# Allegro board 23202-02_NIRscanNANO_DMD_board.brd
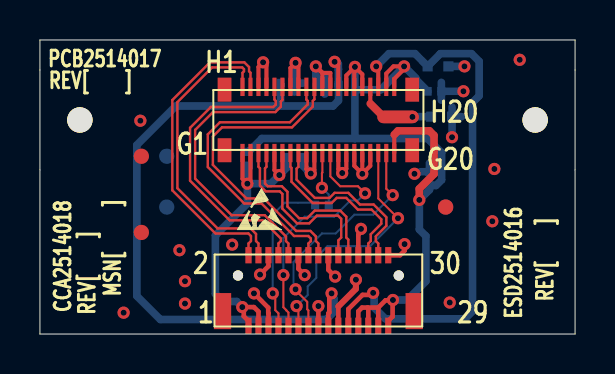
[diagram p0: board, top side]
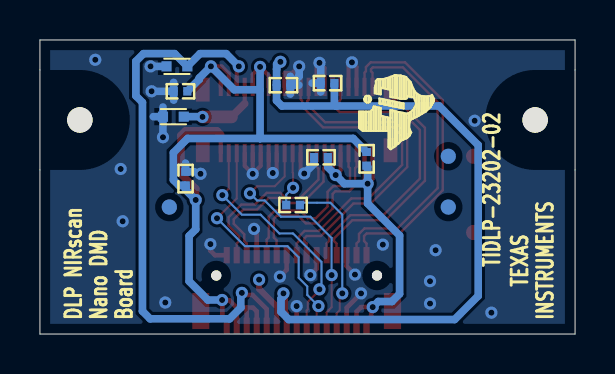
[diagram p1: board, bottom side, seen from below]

Outline 26.8 x 14.71 mm; copper layers: TOP, LY2GND, LY3PLANE, BOTTOM. Coordinates in mm from the lower left corner of the outline.
Outline path: 0,14.71 0,0 26.8,0 26.8,14.71 0,14.71

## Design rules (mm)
net group DIFFPAIR0: nets DMD_HS_WDATAA_N DMD_HS_WDATAA_P
net group DMD_HS_CLK_: nets DMD_HS_CLK_N DMD_HS_CLK_P
net group DMD_HS_WDATAB_: nets DMD_HS_WDATAB_N DMD_HS_WDATAB_P
net group DMD_HS_WDATAG_: nets DMD_HS_WDATAG_N DMD_HS_WDATAG_P
net group DMD_HS_WDATAH_: nets DMD_HS_WDATAH_N DMD_HS_WDATAH_P
net group 68OHM: nets DMD_DEN_ARSTZ DMD_LS_CLK DMD_LS_RDATA DMD_LS_RDATA_T DMD_LS_WDATA
net group PWR: nets VBIAS VCC VCCI VOFS VRST

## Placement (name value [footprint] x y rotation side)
C1  -  [0201]  12.73 8.84 0 bottom
C2  -  [0201]  19.51 7.77 90 bottom
C3  -  [0201]  19.76 12.14 0 bottom
C4  -  [0402]  20.12 10.87 0 bottom
C5  -  [0201]  12.4 12.55 0 bottom
C6  -  [0201]  14.61 12.45 180 bottom
C7  -  [0402]  19.94 13.39 0 bottom
FID  -  [unnamed#3]  5.08 8.89 0 top
FID#2  -  [unnamed#3]  20.32 6.35 0 top
FID#3  -  [unnamed#3]  5.08 5.08 0 top
FID#4  -  [unnamed#3]  20.32 6.35 180 bottom
FID#5  -  [unnamed#3]  6.35 8.89 180 bottom
FID#6  -  [unnamed#3]  6.35 6.35 180 bottom
J1  -  [CONN30-JMCS-G-1B-TF_JST]  13.94 2.18 0 top
J2  -  [CONN40-AXT540124-GH_PAN]  13.94 10.71 0 top
NOREF  -  []  0 0 0 top
NOREF#2  -  [unnamed#2]  2 10.71 0 top
NOREF#3  -  []  11.1 6.15 0 top
NOREF#4  -  []  0 0 0 top
NOREF#5  -  []  67.55 13.92 0 top
NOREF#6  -  []  0 0 90 top
NOREF#7  -  []  -19.05 31.75 0 top
NOREF#8  -  []  44.45 31.75 0 top
NOREF#9  -  []  -115.46 -53.59 0 top
NOREF#10  -  [unnamed#2]  24.8 10.71 0 top
NOREF#11  -  []  -19.05 -12.7 0 top
NOREF#12  -  []  0 0 90 top
NOREF#13  -  []  9.19 11.15 90 bottom
R1  -  [0201]  10.44 8.76 90 bottom
R2  -  [0201]  14.12 6.45 0 bottom

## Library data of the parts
C1-C3 C5 C6 R1 R2 = 0201
C4 C7 = 0402: alternate symbols: (0402-1mm)
J1 = CONN30-JMCS-G-1B-TF_JST
J2 = CONN40-AXT540124-GH_PAN

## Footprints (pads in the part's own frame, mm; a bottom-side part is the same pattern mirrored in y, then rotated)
0201
  rect 0.406x0.432 smd: 1(-0.343,0) 2(0.343,0)
0402
  rect 0.508x0.508 smd: 1(-0.521,0) 2(0.521,0)
CONN30-JMCS-G-1B-TF_JST
  round 0.508 hole 0.686 unplated: (-4.025,0.75) (4.025,0.75)
  rect 0.305x0.813 smd: 1(-3.5,-1.765) 2(-3.5,1.765) 3(-3,-1.765) 4(-3,1.765) 5(-2.5,-1.765) 6(-2.5,1.765) 7(-2,-1.765) 8(-2,1.765) 9(-1.5,-1.765) 10(-1.5,1.765) 11(-1,-1.765) 12(-1,1.765) 13(-0.5,-1.765) 14(-0.5,1.765) 15(0,-1.765) 16(0,1.765) 17(0.5,-1.765) 18(0.5,1.765) 19(1,-1.765) 20(1,1.765) 21(1.5,-1.765) 22(1.5,1.765) 23(2,-1.765) 24(2,1.765) 25(2.5,-1.765) 26(2.5,1.765) 27(3,-1.765) 28(3,1.765) 29(3.5,-1.765) 30(3.5,1.765)
  rect 0.864x1.803 smd: 31(-4.8,-1.03) 32(4.8,-1.03)
CONN40-AXT540124-GH_PAN
  rect 0.686x1.194 smd: 41(-4.7,1.515) 42(-4.7,-1.515) 43(4.7,1.515) 44(4.7,-1.515)
  rect 0.203x0.914 smd: G1(-3.8,-1.655) G2(-3.4,-1.655) G3(-3,-1.655) G4(-2.6,-1.655) G5(-2.2,-1.655) G6(-1.8,-1.655) G7(-1.4,-1.655) G8(-1,-1.655) G9(-0.6,-1.655) G10(-0.2,-1.655) G11(0.2,-1.655) G12(0.6,-1.655) G13(1,-1.655) G14(1.4,-1.655) G15(1.8,-1.655) G16(2.2,-1.655) G17(2.6,-1.655) G18(3,-1.655) G19(3.4,-1.655) G20(3.8,-1.655) H1(-3.8,1.655) H2(-3.4,1.655) H3(-3,1.655) H4(-2.6,1.655) H5(-2.2,1.655) H6(-1.8,1.655) H7(-1.4,1.655) H8(-1,1.655) H9(-0.6,1.655) H10(-0.2,1.655) H11(0.2,1.655) H12(0.6,1.655) H13(1,1.655) H14(1.4,1.655) H15(1.8,1.655) H16(2.2,1.655) H17(2.6,1.655) H18(3,1.655) H19(3.4,1.655) H20(3.8,1.655)
unnamed#2
  round 1.27 hole 2.499 unplated: (0,0)
unnamed#3
  round 0.762 smd: 1(0,0)

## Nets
GND: C1.2 C2.2 C3.2 C4.2 C5.2 C6.2 C7.2 J1.5 J1.6 J1.12 J1.15 J1.18 J1.24 J1.30 J2.G9 J2.G10 J2.G13 J2.G14 J2.G15 J2.G16 J2.G17 J2.H3 J2.H4 J2.H7 J2.H8 J2.H11 J2.H12
VCC: C2.1 C3.1 J1.23 J1.25 J1.27 J1.29 J2.G20 J2.H14 J2.H15 J2.H16 J2.H19 J2.H20 R1.2
VCCI: C1.1 J1.1 J1.3 J2.G1 J2.G2 J2.G5 J2.G6 R1.1
DMD_DEN_ARSTZ: J1.9 J2.G12
DMD_HS_CLK_N: J1.14 J2.H9
DMD_HS_CLK_P: J1.16 J2.H10
DMD_HS_WDATAA_N: J1.4 J2.H1
DMD_HS_WDATAA_P: J1.2 J2.H2
DMD_HS_WDATAB_N: J1.8 J2.H5
DMD_HS_WDATAB_P: J1.10 J2.H6
DMD_HS_WDATAG_N: J1.28 J2.G8
DMD_HS_WDATAG_P: J1.26 J2.G7
DMD_HS_WDATAH_N: J1.22 J2.G4
DMD_HS_WDATAH_P: J1.20 J2.G3
DMD_LS_CLK: J1.13 J2.G19
DMD_LS_RDATA: J1.7 R2.1
DMD_LS_RDATA_T: J2.G11 R2.2
DMD_LS_WDATA: J1.11 J2.G18
VBIAS: C4.1 J1.19 J2.H17
VOFS: C5.1 C6.1 J1.17 J2.H13
VRST: C7.1 J1.21 J2.H18

Pads without a net: FID 1; FID#2 1; FID#3 1; FID#4 1; FID#5 1; FID#6 1; J1 31 32; J2 41 42 43 44

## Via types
v1: diameter 0.61, hole 0.305, TOP to BOTTOM, 48 vias

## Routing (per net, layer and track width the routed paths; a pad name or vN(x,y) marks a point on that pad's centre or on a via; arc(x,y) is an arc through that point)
GND: length 35.3
  TOP w0.203: J2.G14 15.34,8.26 v1(15.14,8.05) 14.94,8.25 J2.G13 ; J2.G10 13.74,8.21 v1(13.56,8.03) 13.34,8.25 J2.G9 ; J2.G17 16.54,8.41 v1(16.14,8.01) ; J2.H8 12.94,13.42 v1(12.8,13.56) 12.54,13.31 J2.H7 ; J2.H3 10.94,13.36 v1(11.18,13.59) 11.34,13.42 J2.H4 ; J2.G15 15.74,8.41 v1(16.14,8.01) ; J2.H11 14.14,13.06 14.54,13.06 J2.H12 ; v1(16.14,8.01) J2.G16
  TOP w0.229: J1.15 v1(13.94,1.4) ; J1.24 15.94,4.97 16.08,5.11 v1(16.08,5.26) ; 14.14,13.06 v1(13.82,13.39) ; v1(14.78,2.87) 14.44,3.21 J1.18 ; v1(10.72,2.03) 11.43,1.32 11.43,1.05 11.44,1.04 J1.5 ; v1(11.02,2.97) 11.44,3.39 J1.6 ; J1.12 12.94,3.26 v1(13.26,2.95) ; J1.30 18.03,3.94 18.26,4.17 v1(18.26,4.5)
  BOTTOM w0.381: v1(13.56,8.03) 13.07,8.52 C1.2 ; 13.83,12.45 C6.2 ; C6.2 14.26,12.89 ; C6.2 13.82,12.89 v1(13.82,13.39) ; C6.2 14.26,12 ; C5.2 12.74,13.5 v1(12.8,13.56) ; C5.2 12.74,12.1 ; C5.2 13.17,12.55 ; C3.2 v1(21.21,12.14) ; C3.2 20.1,12.59 ; C3.2 20.1,11.7 ; C4.2 21.12,10.87 ; C4.2 20.64,11.35 ; C4.2 v1(20.64,9.84) ; 19.06,8.12 C2.2 19.51,8.55 ; C7.2 v1(21.26,13.39)
  vias: v1(4.19,1.07) v1(5.03,10.67) v1(6.99,4.19) v1(7.26,2.64) v1(7.26,1.52) v1(9.63,4.47) v1(18.76,8.01) v1(20.52,1.57) v1(22.66,5.64) v1(22.76,8.26) v1(24.03,13.72)
VCC: length 46.6
  TOP w0.203: J2.H19 17.34,13.03 17.7,13.39 18.11,13.39 18.24,13.25 17.74,12.76 J2.H20 ; J2.H15 15.74,13.33 15.34,12.93 J2.H14 ; v1(15.78,13.36) 16.14,12.99 J2.H16 ; J2.G20 17.74,9.97
  TOP w0.229: J1.29 17.44,0.66 17.66,0.87 17.66,1.69 ; 17.66,1.69 17.31,1.69 16.94,1.32 ; 17.66,1.69 v1(17.68,1.7) ; J1.27 16.94,1.32 16.94,1.32 ; 16.94,1.32 16.41,1.32 ; 16.41,1.32 16.44,1.28 J1.25 ; 16.41,1.32 16.13,1.32 15.94,1.14 J1.23 ; 18.24,13.25 v1(18.24,13.39) ; 15.74,13.33 v1(15.78,13.36)
  TOP w0.381: 17.74,9.97 17.93,10.16 19.51,10.16 19.74,9.93 19.74,8 19,7.26 v1(19,6.71)
  BOTTOM w0.381: 15.78,9.78 19.4,9.78 20.12,9.07 20.12,7.71 19.84,7.43 C2.1 19.51,7.21 v1(19,6.71) 19,5.23 19.33,4.9 19.33,2.64 18.39,1.7 v1(17.68,1.7) ; 15.78,9.78 15.77,9.78 11.11,9.78 R1.2 ; 15.78,9.78 15.78,12.22 ; C3.1 18.82,12.74 18.82,12.8 v1(18.24,13.39) 17.07,12.22 15.78,12.22 ; 15.78,12.22 v1(15.78,13.36)
VCCI: length 19.8
  TOP w0.203: J2.G1 10.14,7.76 v1(10.39,7.52) 10.54,7.67 J2.G2 ; J2.G5 11.74,8.19 v1(11.99,7.95) 12.14,8.11 J2.G6
  TOP w0.229: J1.3 10.94,1.12 10.72,1.35 v1(10.13,1.35) 10.21,1.27 10.21,0.89 10.44,0.66 J1.1
  BOTTOM w0.381: v1(10.39,7.52) 11.56,7.52 v1(11.99,7.95) 12.38,8.34 C1.1 ; v1(10.39,7.52) 10.39,8.37 R1.1 ; v1(10.39,7.52) 10.39,6.53 8.79,4.93 8.79,2.01 9.17,1.63 9.86,1.63 v1(10.13,1.35)
DMD_DEN_ARSTZ: length 12.8
  TOP w0.102: v1(12.19,2.95) 12.19,1.34 12.34,1.2 12.34,1.18 12.44,1.07 J1.9 ; J2.G12 14.54,7.88 15.04,7.39 15.93,7.39 v1(16.28,7.04)
  BOTTOM w0.102: v1(16.28,7.04) 15.93,6.68 15.54,6.68 14.73,5.87 13.26,5.87 12.19,4.8 v1(12.19,2.95)
DMD_HS_CLK_N: length 15.7
  TOP w0.119: J2.H9 13.34,11.73 13.41,11.66 13.41,11.48 12.52,10.59 9.01,10.59 8.41,9.99 8.41,8.35 10.23,6.53 11.1,6.53 12.73,4.9 13.44,4.9 13.57,4.77 13.57,4.65 13.44,4.53 J1.14
DMD_HS_CLK_P: length 15.7
  TOP w0.119: J1.16 13.94,4.53 13.82,4.65 13.82,4.88 13.55,5.16 12.83,5.16 11.21,6.78 10.34,6.78 8.66,8.46 8.66,9.88 9.12,10.34 12.62,10.34 13.67,11.38 13.67,11.66 13.74,11.74 J2.H10
DMD_HS_WDATAA_N: length 15.3
  TOP w0.119: J1.4 10.94,4.53 10.82,4.65 10.82,5.01 10.54,5.28 8.89,5.28 6.88,7.29 6.88,11.6 8.62,13.34 10.13,13.34 10.22,13.25 10.22,13.14 10.14,13.07 J2.H1
DMD_HS_WDATAA_P: length 16.2
  TOP w0.119: J2.H2 10.54,13.07 10.47,13.14 10.47,13.35 10.24,13.59 8.52,13.59 6.63,11.7 6.63,7.19 8.79,5.03 10.44,5.03 10.57,4.9 10.57,4.65 10.44,4.53 J1.2
DMD_HS_WDATAB_N: length 15
  TOP w0.119: J1.8 11.94,4.53 12.07,4.65 12.07,4.77 11.15,5.69 9.5,5.69 7.52,7.67 7.52,10.31 8.56,11.35 11.69,11.35 11.81,11.48 11.81,11.66 11.74,11.72 J2.H5
DMD_HS_WDATAB_P: length 15
  TOP w0.119: J2.H6 12.14,11.71 12.06,11.63 12.06,11.37 11.79,11.1 8.67,11.1 7.77,10.21 7.77,7.77 9.6,5.94 11.26,5.94 12.32,4.88 12.32,4.65 12.44,4.53 J1.10
DMD_HS_WDATAG_N: length 9
  TOP w0.119: J1.28 16.94,4.53 16.82,4.65 16.82,4.88 17.35,5.41 17.35,5.84 16.71,6.48 16.03,6.48 15.44,7.06 14.76,7.06 14.5,6.81 13.77,6.81 12.85,7.72 12.85,8.27 12.94,8.36 J2.G8
DMD_HS_WDATAG_P: length 9
  TOP w0.119: J1.26 16.44,4.53 16.57,4.65 16.57,4.99 17.09,5.52 17.09,5.74 16.61,6.22 15.92,6.22 15.34,6.81 14.86,6.81 14.61,6.55 13.66,6.55 12.6,7.62 12.6,8.31 12.54,8.36 J2.G7
DMD_HS_WDATAH_N: length 9
  TOP w0.119: J2.G4 11.34,8.36 11.27,8.29 11.27,7.53 11.41,7.39 12.12,7.39 12.4,7.11 12.4,6.38 12.98,5.79 13.38,5.79 13.76,6.17 15.04,6.17 15.34,5.87 15.34,4.83 15.44,4.72 J1.22
DMD_HS_WDATAH_P: length 9
  TOP w0.119: J2.G3 10.94,8.36 11.02,8.29 11.02,7.42 11.3,7.14 12.01,7.14 12.14,7.01 12.14,6.27 12.87,5.54 13.49,5.54 13.87,5.92 14.93,5.92 15.09,5.76 15.09,4.83 14.94,4.68 J1.20
DMD_LS_CLK: length 12.1
  TOP w0.102: v1(17.67,6.95) 17.34,7.27 J2.G19 ; J1.13 13.44,1.18 13.39,1.24 13.39,1.61 12.8,2.19 v1(12.8,2.24)
  BOTTOM w0.102: v1(17.67,6.95) 16.69,5.97 15.75,5.97 14.81,5.03 14.12,5.03 12.7,3.61 12.7,2.34 v1(12.8,2.24)
DMD_LS_RDATA: length 8.1
  TOP w0.102: J1.7 11.94,1.03 11.79,1.19 11.79,1.91 v1(11.66,2.03)
  BOTTOM w0.102: v1(11.66,2.03) 11.66,5.97 12.26,6.57 13.67,6.57 R2.1
DMD_LS_RDATA_T: length 2.8
  TOP w0.102: J2.G11 14.14,8.07 14.12,8.05 v1(14.12,7.32)
  BOTTOM w0.102: R2.2 14.47,6.97 v1(14.12,7.32)
DMD_LS_WDATA: length 12.4
  TOP w0.102: J2.G18 16.94,6.78 v1(17.93,5.79) ; J1.11 12.94,1.25 12.85,1.35 v1(12.85,1.4)
  BOTTOM w0.102: v1(12.85,1.4) 13.41,1.96 13.41,2.38 13.84,2.81 13.84,3.84 14.4,4.39 16.54,4.39 v1(17.93,5.79)
VBIAS: length 22.2
  TOP w0.203: J2.H17 16.54,11.52
  TOP w0.229: J1.19 14.94,1.38
  TOP w0.305: v1(15.82,2.72) 15.82,2.26 14.94,1.38
  TOP w0.381: 16.54,11.52 17.21,10.86
  TOP w0.635: 17.21,10.86 v1(18.66,10.86)
  LY3PLANE w0.635: v1(15.82,2.72) 15.9,2.64 15.9,1.5 16.56,0.84 18.44,0.84 20.07,2.46
  LY3PLANE w0.889: v1(18.66,10.86) 18.66,10.07 20.07,8.66 20.07,2.46
  BOTTOM w0.381: v1(18.66,10.86) 18.67,10.87 C4.1
VOFS: length 36.4
  TOP w0.203: J2.H13 14.94,13.5 14.86,13.59 14.78,13.59 v1(14.76,13.61)
  TOP w0.229: J1.17 14.44,1.03 14.49,1.08 14.49,1.92 v1(14.61,2.03)
  BOTTOM w0.381: 11.96,11.4 14.68,11.4 14.95,11.67 14.95,12.44 C6.1 14.95,13.25 14.94,13.25 14.94,13.5 14.86,13.59 14.78,13.59 v1(14.76,13.61) ; 11.96,11.4 6.81,11.4 4.85,9.45 4.85,1.91 6.03,0.72 14.34,0.72 14.73,1.11 14.73,1.77 14.61,1.89 v1(14.61,2.03) ; 11.96,11.4 12.05,11.49 C5.1
VRST: length 28.3
  TOP w0.203: v1(16.84,13.39) 16.94,13.28 J2.H18
  TOP w0.229: J1.21 15.44,1.25 16.15,1.96 16.59,1.96 v1(16.69,2.06)
  BOTTOM w0.381: v1(16.84,13.39) 17.48,14.02 18.78,14.02 C7.1 20.05,14.02 21.62,14.02 22,13.64 22,11.91 21.67,11.58 21.67,1.14 21.29,0.76 17.3,0.76 16.74,1.32 16.74,2.01 v1(16.69,2.06)

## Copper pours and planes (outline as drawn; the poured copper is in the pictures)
GND on BOTTOM: 0.51,14.2 26.29,14.2 26.29,0.51 0.51,0.51 ; 1 cut-out
GND on LY2GND, LY3PLANE: 0.51,14.2 26.29,14.2 26.29,0.51 0.51,0.51

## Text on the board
BOTTOM: LAYER 4 - SECONDARY SIDE | 4
Board Geometry/Soldermask Bottom: SOLDERMASK - SECONDARY SIDE | 6
Ref Des/Silkscreen Bottom: INSTRUMENTS | TEXAS | TIDLP-23202-02 | Board | Nano DMD | DLP NIRscan | SILKSCREEN-SECONDARY SIDE | 8
TOP: LAYER 1 - PRIMARY SIDE | 1
Board Geometry/Soldermask Top: SOLDERMASK - PRIMARY SIDE | 5
Ref Des/Silkscreen Top: PCB2514017 | REV[    ] | CCA2514018 | MSN[     ] | ESD2514016 | SILKSCREEN - PRIMARY SIDE | 7
LY2GND: LAYER 2 - GND PLANE | 2
LY3PLANE: LAYER 3 - GND/PWR PLANE | 3
DIMENSION: (OZ) | SOLDERPASTE - PRIMARY SIDE | RATING AND BE MARKED IN COPPER ON THE TOP SIDE OF THE | BOARD IN INDICATED AREA. | MATERIAL SHALL MEET A MINIMUM OF UL796 AND 94V-0 FLAMMABILITY | 9 | 11 | DIMENSION TOLERANCES ARE +/- 0.010". | 3. SOLDERMASK ARTWORK HAS ZERO (0) OVERSIZED PADS. | FABRICATION VENDOR IS ALLOWED TO ADJUST THE COMPONENT | SOLDERMASK PADS TO MEET THEIR TOOLING REQUIREMENTS | WHILE MAINTAINING WEBBING BETWEEN ADJACENT PADS. | LAYER 1 - PRIMARY SIDE - SIGNAL | LAYER 2 - GND PLANE | LAYER 3 - GND/PWR PLANE | LAYER 4 - SECONDARY SIDE - SIGNAL/ | LAYER# | PLANE | COPPER WEIGHT | HALF+PLATING | 1 | IMPEDANCE CONTROL | +/- 10% | 68ohm SINGLE ENDED | 4 | 75ohm SINGLE ENDED | PRIMARY SIDE VIEW | 100ohm DIFFERENTIAL | 4.7/5.3 | FAB DRAWING | 0 | LAYER STACK-UP - ALL DIMENSIONS IN INCHES
PASTEMASK_BOTTOM: SOLDERPASTE - SECONDARY SIDE | 10
User.11: 19 | TOP SIDE VIA PLUG
User.18: ASSEMBLY
User.19: ASSEMBLY
User.22: 29 OCT 2014 | 11 | NIRscan Nano DMD Board | 2514018 | - | TEXAS INSTRUMENTS
User.43: FIGURE | SIZE | 12.0 | 27.0 | 98.4 | DRILL CHART: TOP to BOTTOM | ALL UNITS ARE IN MILS | TOLERANCE | +3.0/-12.0 | +3.0/-3.0 | PLATED | NON-PLATED | QTY | 48 | 2
